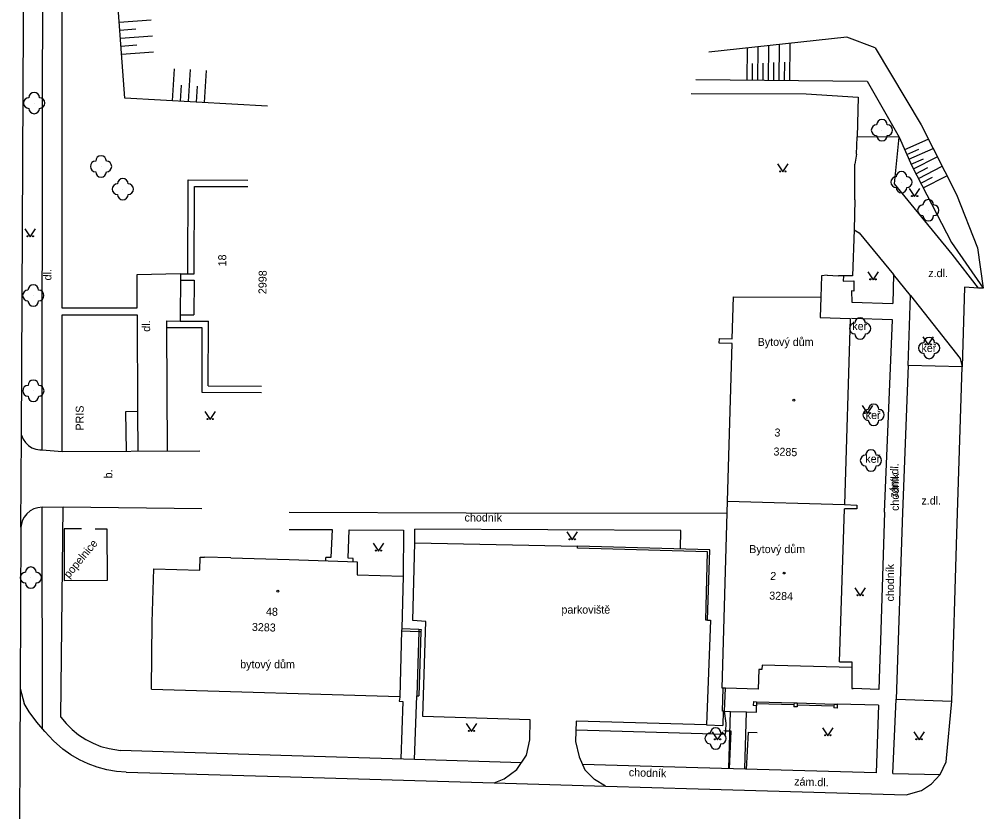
# Model space of a CAD drawing. Extents: x -584400 to -581602, y -1210894 to -1208793.
# Drawn here: x -582837.7 to -582747.8, y -1209957.3 to -1209883 of the extents above; entities that cross this region are included whole.
import ezdxf

# ---------------------------------------------------------------- set-up
doc = ezdxf.new("R2010")
doc.units = 0
for name, color, linetype in [('BUDOVY_MĚŘ', 7, 'Continuous'), ('POMOC_POPIS', 7, 'Continuous'), ('ROZHRANÍ_PLOCH', 7, 'Continuous'), ('VÝŠKOPIS', 7, 'Continuous'), ('ZELEŇ', 7, 'Continuous'), ('ZN_BUDOV', 7, 'Continuous'), ('ZN_DOPLŇKOVÉ', 7, 'Continuous'), ('ZN_KULTUR', 7, 'Continuous'), ('Č_POPIS_EVID', 7, 'Continuous')]:
    doc.layers.add(name, color=color, linetype=linetype)

msp = doc.modelspace()

# ---------------------------------------------------------------- linework, layer by layer
at = {"layer": 'BUDOVY_MĚŘ'}
for points in [[(-582822.57, -1209906.86), (-582821.29, -1209906.87), (-582821.26, -1209898.67), (-582816.26, -1209898.69)], [(-582822.57, -1209906.86), (-582822.59, -1209911.29), (-582819.95, -1209911.3)], [(-582771.3, -1209928.16), (-582770.88, -1209913.38), (-582772.08, -1209913.35), (-582772.07, -1209912.91), (-582770.87, -1209912.94), (-582770.74, -1209909.01), (-582762.56, -1209909.06), (-582762.62, -1209910.96), (-582759.8, -1209911.05), (-582760.35, -1209928.49)], [(-582819.98, -1209917.36), (-582819.95, -1209911.3)], [(-582819.98, -1209917.36), (-582814.98, -1209917.38)], [(-582760.8, -1209943.22), (-582759.64, -1209943.22), (-582759.64, -1209943.76), (-582768.06, -1209943.54), (-582768.08, -1209943.94), (-582768.38, -1209943.94), (-582768.43, -1209945.78), (-582771.5, -1209945.7), (-582771.7, -1209945.7), (-582771.82, -1209945.7), (-582771.3, -1209928.16)], [(-582771.3, -1209928.16), (-582760.35, -1209928.49)], [(-582760.35, -1209928.49), (-582759.18, -1209928.53), (-582759.19, -1209928.88), (-582760.35, -1209928.87)], [(-582760.8, -1209943.22), (-582760.35, -1209928.87)], [(-582825.28, -1209945.79), (-582825.22, -1209939.51), (-582825.07, -1209934.51), (-582820.76, -1209934.64), (-582820.73, -1209933.4), (-582820.33, -1209933.41)], [(-582817.85, -1209933.47), (-582812.38, -1209933.64), (-582806, -1209933.84), (-582806.03, -1209935.06), (-582801.71, -1209935.19), (-582801.84, -1209940.11), (-582801.85, -1209940.31), (-582802.02, -1209946.48)], [(-582825.28, -1209945.79), (-582802.02, -1209946.48)], [(-582802.02, -1209946.48), (-582802.02, -1209946.53)], [(-582768.88, -1209946.95), (-582768.58, -1209946.96), (-582768.59, -1209947.16), (-582768.59, -1209947.33), (-582768.89, -1209947.32)], [(-582768.88, -1209946.95), (-582768.89, -1209947.32)], [(-582765.07, -1209947.06), (-582764.77, -1209947.07), (-582764.78, -1209947.27), (-582764.78, -1209947.44), (-582765.08, -1209947.43)], [(-582765.07, -1209947.06), (-582765.08, -1209947.26), (-582765.08, -1209947.43)], [(-582761.32, -1209947.17), (-582761.02, -1209947.18), (-582761.03, -1209947.55), (-582761.33, -1209947.54)], [(-582761.32, -1209947.17), (-582761.33, -1209947.37), (-582761.33, -1209947.54)]]:
    msp.add_lwpolyline(points, dxfattribs=at)
at = {"layer": 'ROZHRANÍ_PLOCH'}
for points in [[(-582837.47, -1209921.98), (-582837.29, -1209883.42), (-582836.97, -1209858.16)], [(-582835.55, -1209923.37), (-582835.49, -1209889.79), (-582835.39, -1209858.17), (-582836.97, -1209858.16)], [(-582822.57, -1209906.86), (-582826.66, -1209906.95), (-582826.65, -1209910.08), (-582833.67, -1209910.08), (-582833.65, -1209872.69), (-582832.75, -1209872.74)], [(-582757.47, -1209885.68), (-582753.16, -1209892.91), (-582749.85, -1209899.43), (-582747.87, -1209904.42), (-582747.36, -1209908.22)], [(-582755.21, -1209894.05), (-582759.15, -1209894.03)], [(-582747.77, -1209908.21), (-582750.25, -1209905.03), (-582755.65, -1209898.42), (-582755.21, -1209894.05)], [(-582821.89, -1209906.86), (-582821.86, -1209898.07), (-582816.26, -1209898.09)], [(-582759.45, -1209902.74), (-582758.98, -1209903.03), (-582755.74, -1209906.92)], [(-582760.44, -1209907.05), (-582760.47, -1209907.55), (-582759.48, -1209907.53), (-582759.46, -1209908.49), (-582759.68, -1209908.47), (-582759.66, -1209909.53), (-582755.81, -1209909.63)], [(-582755.74, -1209906.92), (-582755.81, -1209909.63)], [(-582754.16, -1209908.9), (-582755.74, -1209906.92)], [(-582822.57, -1209907.46), (-582821.29, -1209907.47), (-582821.31, -1209910.7)], [(-582747.36, -1209908.22), (-582747.77, -1209908.21), (-582749.09, -1209908.12), (-582749.33, -1209915.59)], [(-582754.36, -1209915.45), (-582754.16, -1209908.9), (-582749.51, -1209914.8), (-582749.33, -1209915.59)], [(-582833.65, -1209923.51), (-582833.66, -1209910.7), (-582826.64, -1209910.69), (-582826.6, -1209919.77)], [(-582822.59, -1209910.69), (-582821.31, -1209910.7)], [(-582823.84, -1209911.88), (-582823.84, -1209911.28), (-582822.59, -1209911.29)], [(-582756.58, -1209929.21), (-582755.84, -1209911.16), (-582759.7, -1209911.05)], [(-582823.78, -1209923.46), (-582823.84, -1209911.88)], [(-582823.84, -1209911.88), (-582820.56, -1209911.9), (-582820.58, -1209917.96), (-582814.98, -1209917.98)], [(-582754.36, -1209915.45), (-582754.92, -1209929.23)], [(-582749.33, -1209915.59), (-582754.36, -1209915.45)], [(-582749.81, -1209931.24), (-582749.33, -1209915.59)], [(-582826.6, -1209919.77), (-582827.73, -1209919.78), (-582827.67, -1209923.48)], [(-582826.6, -1209919.77), (-582826.58, -1209923.47)], [(-582837.53, -1209930.59), (-582837.47, -1209921.98)], [(-582837.47, -1209921.98), (-582837.32, -1209922.34), (-582837.11, -1209922.67), (-582836.83, -1209922.95), (-582836.5, -1209923.16), (-582836.14, -1209923.3), (-582835.75, -1209923.37), (-582835.55, -1209923.37)], [(-582835.55, -1209923.37), (-582833.65, -1209923.51)], [(-582833.65, -1209923.51), (-582820.76, -1209923.45)], [(-582835.54, -1209928.74), (-582835.94, -1209928.78), (-582836.32, -1209928.89), (-582836.67, -1209929.08), (-582836.97, -1209929.34), (-582837.22, -1209929.65), (-582837.4, -1209930), (-582837.53, -1209930.59)], [(-582835.54, -1209928.74), (-582833.57, -1209928.69)], [(-582835.51, -1209949.51), (-582835.54, -1209928.74)], [(-582833.79, -1209948.4), (-582833.57, -1209928.69)], [(-582833.57, -1209928.69), (-582820.57, -1209928.85)], [(-582771.34, -1209929.31), (-582795.81, -1209929.28), (-582812.38, -1209929.23)], [(-582756.58, -1209929.21), (-582756.97, -1209941.24), (-582757.05, -1209943.84), (-582757.12, -1209945.8), (-582759.54, -1209945.72)], [(-582754.92, -1209929.23), (-582755.49, -1209946.72)], [(-582837.53, -1209930.59), (-582837.6, -1209945.72)], [(-582812.38, -1209930.83), (-582808.37, -1209930.83), (-582808.47, -1209933.43), (-582808.95, -1209933.44)], [(-582806.4, -1209933.83), (-582806.39, -1209933.53), (-582806.86, -1209933.49), (-582806.77, -1209930.84), (-582801.68, -1209930.87), (-582801.71, -1209935.19)], [(-582800.62, -1209932.08), (-582800.61, -1209930.8)], [(-582775.7, -1209932.63), (-582775.68, -1209930.92), (-582800.61, -1209930.8)], [(-582750.29, -1209946.89), (-582749.81, -1209931.24)], [(-582793.17, -1209954.56), (-582792.24, -1209954.17), (-582791.05, -1209953.31), (-582790.15, -1209951.96), (-582789.84, -1209950.54), (-582789.8, -1209948.66), (-582799.87, -1209948.34), (-582799.59, -1209939.43), (-582800.79, -1209939.36), (-582800.62, -1209932.08)], [(-582800.62, -1209932.08), (-582785.36, -1209932.37)], [(-582808.96, -1209933.75), (-582808.95, -1209933.44)], [(-582773.18, -1209939.33), (-582772.91, -1209939.33), (-582773.27, -1209949.13)], [(-582759.64, -1209943.76), (-582759.64, -1209945.72), (-582759.54, -1209945.72)], [(-582837.6, -1209945.72), (-582837.69, -1209964.34)], [(-582837.6, -1209945.72), (-582837.23, -1209947.13)], [(-582802.02, -1209946.53), (-582802.07, -1209946.9), (-582801.74, -1209946.93), (-582801.91, -1209952.32)], [(-582800.63, -1209952.37), (-582800.43, -1209946.39)], [(-582755.82, -1209953.67), (-582755.49, -1209946.72)], [(-582755.49, -1209946.72), (-582750.29, -1209946.89)], [(-582827.67, -1209953.57), (-582828.58, -1209953.49), (-582829.48, -1209953.33), (-582830.37, -1209953.1), (-582831.23, -1209952.79), (-582832.05, -1209952.4), (-582832.85, -1209951.94), (-582833.61, -1209951.41), (-582834.48, -1209950.61), (-582835.29, -1209949.76), (-582836.05, -1209948.86), (-582836.74, -1209947.9), (-582837.23, -1209947.13)], [(-582757.17, -1209947.29), (-582757.37, -1209953.63), (-582774.08, -1209953.16), (-582784.89, -1209952.84)], [(-582769.53, -1209947.91), (-582768.6, -1209947.94), (-582768.59, -1209947.33)], [(-582757.17, -1209947.29), (-582761.02, -1209947.18)], [(-582751.38, -1209953.76), (-582750.81, -1209952.6), (-582750.29, -1209946.89)], [(-582833.79, -1209948.4), (-582833.29, -1209949.01), (-582832.73, -1209949.56), (-582832.12, -1209950.06), (-582831.46, -1209950.49), (-582830.76, -1209950.85), (-582830.03, -1209951.14), (-582829.27, -1209951.35), (-582828.18, -1209951.52)], [(-582771.71, -1209947.84), (-582771.75, -1209949.17)], [(-582771.58, -1209947.85), (-582771.03, -1209947.87)], [(-582771.19, -1209953.2), (-582771.03, -1209947.87)], [(-582771.03, -1209947.87), (-582769.53, -1209947.91)], [(-582769.69, -1209953.25), (-582769.53, -1209947.91)], [(-582773.27, -1209949.13), (-582785.49, -1209948.79), (-582785.54, -1209950.67), (-582785.2, -1209952.13), (-582784.67, -1209953.35), (-582783.76, -1209954.24)], [(-582773.27, -1209949.13), (-582771.75, -1209949.17)], [(-582771.46, -1209949.7), (-582771.66, -1209949.68)], [(-582771.13, -1209953.23), (-582770.96, -1209949.72), (-582771.46, -1209949.7)], [(-582769.53, -1209953.3), (-582769.35, -1209949.81), (-582768.53, -1209949.83)], [(-582800.63, -1209952.37), (-582813.16, -1209952), (-582828.18, -1209951.52)], [(-582790.62, -1209952.67), (-582800.63, -1209952.37)], [(-582827.67, -1209953.57), (-582813.32, -1209953.97), (-582793.17, -1209954.56)], [(-582782.75, -1209954.86), (-582774.05, -1209955.11), (-582754.55, -1209955.68), (-582753.13, -1209955.28), (-582752.19, -1209954.64), (-582751.38, -1209953.76)], [(-582755.82, -1209953.67), (-582751.38, -1209953.76)], [(-582793.17, -1209954.56), (-582782.75, -1209954.86)], [(-582782.75, -1209954.86), (-582783.76, -1209954.24)]]:
    msp.add_lwpolyline(points, dxfattribs=at)
at = {"layer": 'VÝŠKOPIS'}
for points in [[(-582814.43, -1209891.15), (-582827.79, -1209890.39), (-582828.69, -1209878.12), (-582817.23, -1209877.79)], [(-582825.32, -1209883.09), (-582828.31, -1209883.31)], [(-582826.76, -1209883.94), (-582828.26, -1209884.05)], [(-582825.21, -1209884.58), (-582828.2, -1209884.8)], [(-582757.47, -1209885.68), (-582760.13, -1209884.68), (-582773.06, -1209886.09)], [(-582826.65, -1209885.44), (-582828.15, -1209885.55)], [(-582768.46, -1209888.71), (-582768.43, -1209885.59)], [(-582767.46, -1209888.72), (-582767.43, -1209885.48)], [(-582766.46, -1209888.73), (-582766.43, -1209885.37)], [(-582765.46, -1209888.74), (-582765.43, -1209885.26)], [(-582825.1, -1209886.08), (-582828.09, -1209886.3)], [(-582769.46, -1209888.7), (-582769.43, -1209885.7)], [(-582768.96, -1209888.71), (-582768.95, -1209887.17)], [(-582767.96, -1209888.72), (-582767.95, -1209887.12)], [(-582766.96, -1209888.72), (-582766.95, -1209887.07)], [(-582765.96, -1209888.73), (-582765.94, -1209887.02)], [(-582823.17, -1209887.65), (-582823.34, -1209890.64)], [(-582821.68, -1209887.73), (-582821.85, -1209890.73)], [(-582820.18, -1209887.82), (-582820.35, -1209890.81)], [(-582822.51, -1209889.19), (-582822.59, -1209890.69)], [(-582774.29, -1209888.66), (-582758.23, -1209888.8), (-582755.21, -1209894.05)], [(-582821.01, -1209889.27), (-582821.1, -1209890.77)], [(-582755.21, -1209894.05), (-582754.02, -1209896.75), (-582750.32, -1209903.94), (-582747.36, -1209908.22)], [(-582754.7, -1209895.21), (-582752.49, -1209894.24)], [(-582754.5, -1209895.67), (-582753.38, -1209895.18)], [(-582754.3, -1209896.13), (-582752.03, -1209895.13)], [(-582754.09, -1209896.58), (-582752.95, -1209896.08)], [(-582753.87, -1209897.03), (-582751.65, -1209895.89)], [(-582753.65, -1209897.48), (-582752.53, -1209896.91)], [(-582753.42, -1209897.92), (-582751.2, -1209896.78)], [(-582753.19, -1209898.37), (-582752.08, -1209897.8)], [(-582752.96, -1209898.81), (-582750.74, -1209897.67)]]:
    msp.add_lwpolyline(points, dxfattribs=at)
at = {"layer": 'ZELEŇ'}
for centre in [(-582836.29, -1209890.86), (-582756.83, -1209893.4), (-582830.02, -1209896.8), (-582827.98, -1209898.93), (-582755, -1209898.27), (-582752.49, -1209900.91), (-582836.37, -1209908.89), (-582758.88, -1209911.99), (-582752.41, -1209913.82), (-582836.36, -1209917.82), (-582757.61, -1209920.08), (-582757.86, -1209924.35), (-582836.6, -1209935.33), (-582772.42, -1209950.4)]:
    msp.add_circle(centre, 0.0005, dxfattribs=at)
for centre, start, end in [((-582836.29, -1209890.36), 0, 179.99999), ((-582836.79, -1209890.86), 89.99999, 269.99999), ((-582835.79, -1209890.86), 270, 89.99999), ((-582836.29, -1209891.36), 179.99999, 359.99999), ((-582756.83, -1209892.9), 0, 179.99999), ((-582757.33, -1209893.4), 89.99999, 269.99999), ((-582756.33, -1209893.4), 270, 89.99999), ((-582756.83, -1209893.9), 179.99999, 359.99999), ((-582830.52, -1209896.8), 89.99999, 269.99999), ((-582830.02, -1209896.3), 0, 179.99999), ((-582829.52, -1209896.8), 270, 89.99999), ((-582830.02, -1209897.3), 179.99999, 359.99999), ((-582755, -1209897.77), 0, 179.99999), ((-582827.98, -1209898.43), 0, 179.99999), ((-582755.5, -1209898.27), 89.99999, 269.99999), ((-582754.5, -1209898.27), 270, 89.99999), ((-582828.48, -1209898.93), 89.99999, 269.99999), ((-582827.48, -1209898.93), 270, 89.99999), ((-582755, -1209898.77), 179.99999, 359.99999), ((-582827.98, -1209899.43), 179.99999, 359.99999), ((-582752.49, -1209900.41), 0, 179.99999), ((-582752.99, -1209900.91), 89.99999, 269.99999), ((-582751.99, -1209900.91), 270, 89.99999), ((-582752.49, -1209901.41), 179.99999, 359.99999), ((-582836.37, -1209908.39), 0, 179.99999), ((-582836.87, -1209908.89), 89.99999, 269.99999), ((-582835.87, -1209908.89), 270, 89.99999), ((-582836.37, -1209909.39), 179.99999, 359.99999), ((-582759.38, -1209911.99), 89.99999, 269.99999), ((-582758.88, -1209911.49), 0, 179.99999), ((-582758.38, -1209911.99), 270, 89.99999), ((-582758.88, -1209912.49), 179.99999, 359.99999), ((-582752.91, -1209913.82), 89.99999, 269.99999), ((-582752.41, -1209913.32), 0, 179.99999), ((-582751.91, -1209913.82), 270, 89.99999), ((-582752.41, -1209914.32), 179.99999, 359.99999), ((-582836.36, -1209917.32), 0, 179.99999), ((-582836.86, -1209917.82), 89.99999, 269.99999), ((-582835.86, -1209917.82), 270, 89.99999), ((-582836.36, -1209918.32), 179.99999, 359.99999), ((-582758.11, -1209920.08), 89.99998, 269.99998), ((-582757.61, -1209919.58), 359.99998, 179.99998), ((-582757.11, -1209920.08), 269.99998, 89.99997), ((-582757.61, -1209920.58), 179.99998, 359.99997), ((-582757.86, -1209923.85), 0, 179.99999), ((-582758.36, -1209924.35), 89.99999, 269.99999), ((-582757.36, -1209924.35), 270, 89.99999), ((-582757.86, -1209924.85), 179.99999, 359.99999), ((-582837.1, -1209935.33), 89.99999, 269.99999), ((-582836.6, -1209934.83), 0, 179.99999), ((-582836.1, -1209935.33), 270, 89.99999), ((-582836.6, -1209935.83), 179.99999, 359.99999), ((-582772.42, -1209949.9), 359.99998, 179.99998), ((-582772.92, -1209950.4), 89.99998, 269.99998), ((-582771.92, -1209950.4), 269.99998, 89.99997), ((-582772.42, -1209950.9), 179.99998, 359.99997)]:
    msp.add_arc(centre, 0.5, start, end, dxfattribs=at)
at = {"layer": 'ZN_BUDOV'}
for centre in [(-582765.1, -1209918.7), (-582766, -1209934.9), (-582813.45, -1209936.59)]:
    msp.add_circle(centre, 0.0875, dxfattribs=at)
at = {"layer": 'ZN_DOPLŇKOVÉ'}
for points in [[(-582774.72, -1209889.98), (-582763.95, -1209890.01)], [(-582763.95, -1209890.01), (-582759.05, -1209890.32), (-582759.15, -1209894.03)], [(-582759.23, -1209895.64), (-582759.15, -1209894.03)], [(-582759.23, -1209895.64), (-582759.38, -1209896.58)], [(-582759.36, -1209899.94), (-582759.38, -1209896.58)], [(-582759.36, -1209899.94), (-582759.45, -1209902.74), (-582759.59, -1209907.04), (-582760.44, -1209907.05), (-582760.9, -1209907.05)], [(-582761.97, -1209907), (-582762.49, -1209907.06), (-582762.56, -1209909.06)], [(-582761.97, -1209907), (-582760.9, -1209907.05)], [(-582831.84, -1209930.77), (-582833.46, -1209930.77), (-582833.47, -1209935.6), (-582829.41, -1209935.58), (-582829.46, -1209930.79), (-582830.57, -1209930.79)], [(-582773.18, -1209939.33), (-582773.34, -1209939.33), (-582773.17, -1209932.91), (-582785.36, -1209932.57), (-582785.36, -1209932.37)], [(-582773.18, -1209939.33), (-582772.96, -1209932.72), (-582785.36, -1209932.37)], [(-582817.85, -1209933.47), (-582820.33, -1209933.41)], [(-582801.85, -1209940.31), (-582800.24, -1209940.37)], [(-582801.84, -1209940.11), (-582800.23, -1209940.17)], [(-582800.24, -1209940.37), (-582800.43, -1209946.39), (-582800.23, -1209946.4)], [(-582800.23, -1209940.17), (-582800.24, -1209940.37)], [(-582800.24, -1209940.37), (-582800.04, -1209940.38)], [(-582800.23, -1209940.17), (-582800.03, -1209940.18), (-582800.04, -1209940.38)], [(-582800.04, -1209940.38), (-582800.23, -1209946.4)], [(-582771.58, -1209947.85), (-582771.78, -1209947.84), (-582771.7, -1209945.7)], [(-582771.58, -1209947.85), (-582771.5, -1209945.7)], [(-582765.08, -1209947.26), (-582768.59, -1209947.16)], [(-582768.58, -1209946.96), (-582765.07, -1209947.06)], [(-582761.33, -1209947.37), (-582764.78, -1209947.27)], [(-582764.77, -1209947.07), (-582761.32, -1209947.17)], [(-582771.42, -1209948.95), (-582771.58, -1209947.85)], [(-582771.46, -1209949.7), (-582771.42, -1209948.95)], [(-582785.48, -1209949.6), (-582771.48, -1209950.01), (-582771.46, -1209949.7)]]:
    msp.add_lwpolyline(points, dxfattribs=at)
at = {"layer": 'ZN_KULTUR'}
for points in [[(-582766.62, -1209896.57), (-582766.12, -1209897.32), (-582765.62, -1209896.57)], [(-582754.27, -1209898.88), (-582753.77, -1209899.63), (-582753.27, -1209898.88)], [(-582837.15, -1209902.64), (-582836.65, -1209903.39), (-582836.15, -1209902.64)], [(-582758.17, -1209906.68), (-582757.67, -1209907.43), (-582757.17, -1209906.68)], [(-582752.99, -1209912.77), (-582752.49, -1209913.52), (-582751.99, -1209912.77)], [(-582820.3, -1209919.77), (-582819.8, -1209920.52), (-582819.3, -1209919.77)], [(-582758.7, -1209919.21), (-582758.2, -1209919.96), (-582757.7, -1209919.21)], [(-582786.36, -1209931.04), (-582785.86, -1209931.79), (-582785.36, -1209931.04)], [(-582804.52, -1209932.09), (-582804.02, -1209932.84), (-582803.52, -1209932.09)], [(-582759.38, -1209936.28), (-582758.88, -1209937.03), (-582758.38, -1209936.28)], [(-582795.8, -1209948.99), (-582795.3, -1209949.74), (-582794.8, -1209948.99)], [(-582762.4, -1209949.4), (-582761.9, -1209950.15), (-582761.4, -1209949.4)], [(-582772.74, -1209949.78), (-582772.24, -1209950.53), (-582771.74, -1209949.78)], [(-582753.86, -1209949.77), (-582753.36, -1209950.52), (-582752.86, -1209949.77)]]:
    msp.add_lwpolyline(points, dxfattribs=at)
for centre in [(-582766.37, -1209897.27), (-582765.87, -1209897.27), (-582754.02, -1209899.58), (-582753.52, -1209899.58), (-582836.9, -1209903.34), (-582836.4, -1209903.34), (-582757.92, -1209907.38), (-582757.42, -1209907.38), (-582752.74, -1209913.47), (-582752.24, -1209913.47), (-582820.05, -1209920.47), (-582819.55, -1209920.47), (-582758.45, -1209919.91), (-582757.95, -1209919.91), (-582786.11, -1209931.74), (-582785.61, -1209931.74), (-582804.27, -1209932.79), (-582803.77, -1209932.79), (-582759.13, -1209936.98), (-582758.63, -1209936.98), (-582795.55, -1209949.69), (-582795.05, -1209949.69), (-582762.15, -1209950.1), (-582761.65, -1209950.1), (-582772.49, -1209950.48), (-582771.99, -1209950.48), (-582753.61, -1209950.47), (-582753.11, -1209950.47)]:
    msp.add_circle(centre, 0.05, dxfattribs=at)

# ---------------------------------------------------------------- texts
at = {"layer": 'POMOC_POPIS'}
for s, rotation, p in [('dl.', 89.81188, (-582834.67, -1209907.48)), ('dl.', 89.81188, (-582825.42, -1209912.29)), ('PRIS', 89.81188, (-582831.65, -1209921.55)), ('zám.dl.', 88.1334, (-582755.38, -1209927.85)), ('b.', 89.81188, (-582828.97, -1209926.03)), ('chodník', 89.99998, (-582755.25, -1209929.08)), ('popelnice', 50.18274, (-582833.03, -1209935.44)), ('chodník', 89.99998, (-582755.7, -1209937.56)), ('bytový dům', 359.9864, (-582816.98, -1209943.82)), (' chodník', 358.32534, (-582780.84, -1209953.93)), ('zám.dl.', 358.3407, (-582765.07, -1209954.8))]:
    msp.add_text(s, height=0.75, rotation=rotation, dxfattribs=at).set_placement(p)
for s, p in [('z.dl.', (-582752.49, -1209907.17)), ('Bytový dům', (-582768.48, -1209913.62)), ('z.dl.', (-582753.13, -1209928.48)), ('chodník', (-582795.95, -1209930.07)), ('Bytový dům', (-582769.27, -1209933.03)), ('parkoviště', (-582786.87, -1209938.7))]:
    msp.add_text(s, height=0.75, dxfattribs=at).set_placement(p)
at = {"layer": 'ZELEŇ'}
for p in [(-582759.61, -1209912.14), (-582753.13, -1209914.19), (-582758.35, -1209920.47), (-582758.39, -1209924.57)]:
    msp.add_text('keř', height=0.75, dxfattribs=at).set_placement(p)
at = {"layer": 'Č_POPIS_EVID'}
for s, rotation, p in [('18', 89.79028, (-582818.29, -1209906.17)), ('2998', 89.30097, (-582814.52, -1209908.77)), ('3', 355.84375, (-582766.93, -1209922.09)), ('3285', 357.98008, (-582767.01, -1209923.88)), ('2', 355.84375, (-582767.33, -1209935.53)), ('3284', 357.98008, (-582767.41, -1209937.38)), ('48', 358.30082, (-582814.57, -1209938.88)), ('3283', 358.30082, (-582815.89, -1209940.32))]:
    msp.add_text(s, height=0.75, rotation=rotation, dxfattribs=at).set_placement(p)

doc.saveas('drawing.dxf')
